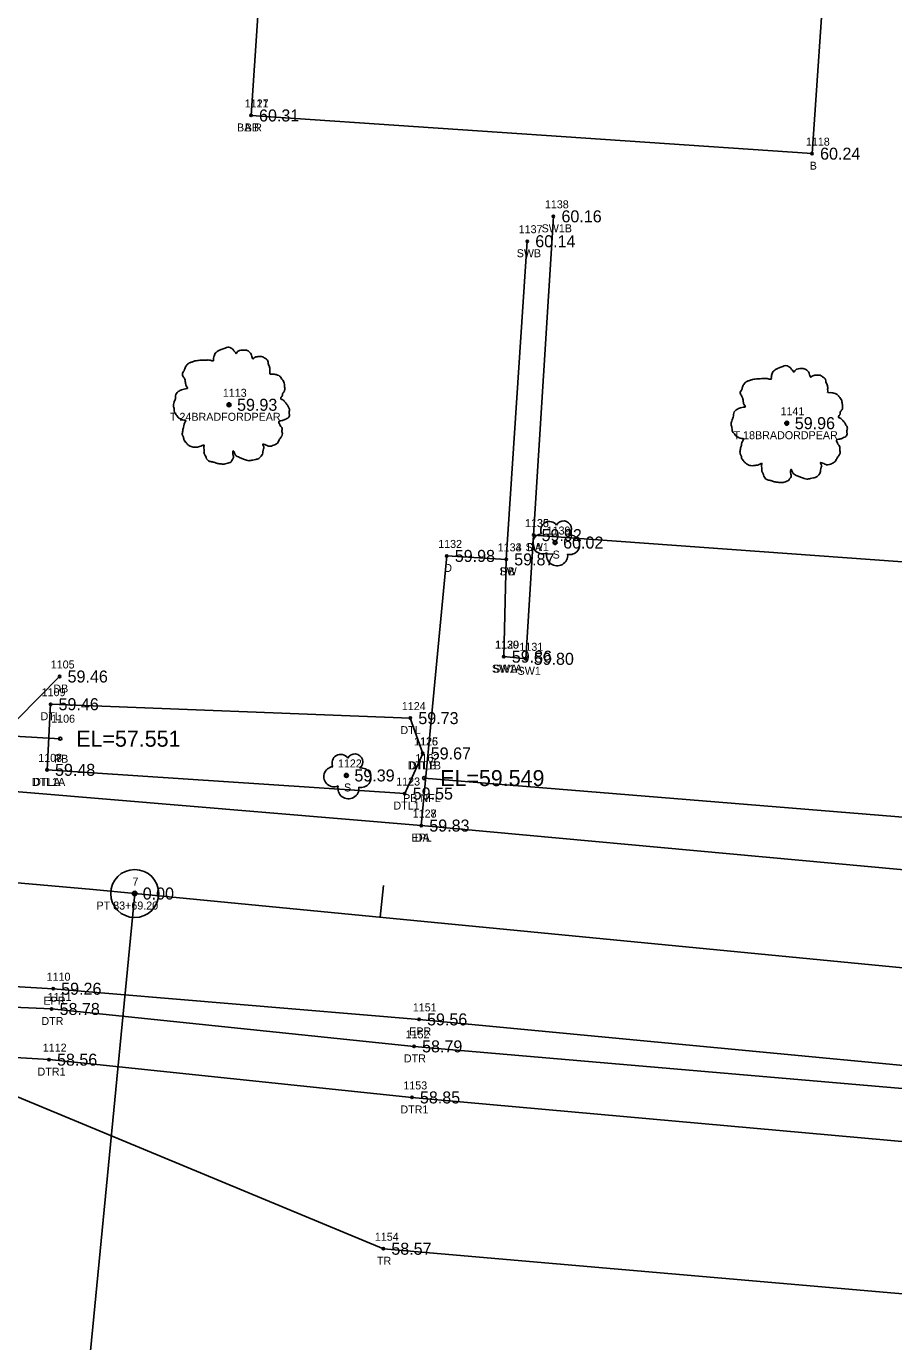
# Model space of a CAD drawing. Extents: x 2420113 to 2422887, y 845323 to 846653.
# Drawn here: x 2420746.1 to 2420854.4, y 845663.2 to 845827.5 of the extents above; entities that cross this region are included whole.
import ezdxf

# ---------------------------------------------------------------- set-up
doc = ezdxf.new("R2010")
doc.units = 0
for name, color, linetype in [('RD_EX_Bldg', 7, 'Continuous'), ('RD_EX_Bldg_txCode', 7, 'Continuous'), ('RD_EX_Conc', 7, 'Continuous'), ('RD_EX_Conc_txCode', 7, 'Continuous'), ('RD_EX_DR_Pipe', 7, 'Continuous'), ('RD_EX_DR_Pipe_txCode', 7, 'Continuous'), ('RD_EX_Driveway', 7, 'Continuous'), ('RD_EX_Driveway_txCode', 7, 'Continuous'), ('RD_EX_H2O', 7, 'Continuous'), ('RD_EX_H2O_txCode', 7, 'Continuous'), ('RD_EX_Road', 7, 'Continuous'), ('RD_EX_Road_txCode', 7, 'Continuous'), ('RD_EX_TX_Bldg_ELEV', 7, 'Continuous'), ('RD_EX_TX_Conc_ELEV', 7, 'Continuous'), ('RD_EX_TX_Driveway_ELEV', 7, 'Continuous'), ('RD_EX_TX_H2O_ELEV', 7, 'Continuous'), ('RD_EX_TX_Road_ELEV', 7, 'Continuous'), ('RD_EX_TX_VEG_ELEV', 7, 'Continuous'), ('RD_EX_VEG', 7, 'Continuous'), ('RD_EX_VEG_txCode', 7, 'Continuous'), ('RD_HC_Cl', 7, 'Continuous'), ('RD_HC_Data', 7, 'Continuous'), ('RD_HC_Data_Tic', 7, 'Continuous'), ('RD_HC_Survey_ELEV', 7, 'Continuous'), ('RD_HC_txCode', 7, 'Continuous'), ('RD_SMD_Locator', 7, 'Continuous'), ('RD_TX_Pipe_ElevEX', 7, 'Continuous')]:
    doc.layers.add(name, color=color, linetype=linetype)

msp = doc.modelspace()

# ---------------------------------------------------------------- linework, layer by layer
at = {"layer": 'RD_EX_Bldg'}
msp.add_lwpolyline([(2420774.14, 845816.35), (2420844.19, 845811.58), (2420845.89, 845836.52), (2420775.84, 845841.29), (2420774.14, 845816.35)], dxfattribs=at)
at = {"layer": 'RD_EX_Conc'}
for points in [[(2420805.7, 845748.75), (2420808.43, 845748.48), (2420809.42, 845763.93), (2420811.9, 845803.75)], [(2420805.7, 845748.75), (2420806, 845760.9), (2420808.63, 845800.64)]]:
    msp.add_lwpolyline(points, dxfattribs=at)
at = {"layer": 'RD_EX_DR_Pipe'}
for p, q in [((2420720.48, 845740.22), (2420750.32, 845738.5)), ((2420903.06, 845724.83), (2420795.76, 845733.58))]:
    msp.add_line(p, q, dxfattribs=at)
at = {"layer": 'RD_EX_Driveway'}
msp.add_line((2420736.67, 845732.56), (2420750.24, 845746.27), dxfattribs=at)
for points in [[(2420809.42, 845763.93), (2420862.38, 845760.08), (2420865.05, 845760.09), (2420893.89, 845756.85), (2420889.7, 845718.98)], [(2420795.4, 845727.65), (2420798.58, 845761.33), (2420806, 845760.9)]]:
    msp.add_lwpolyline(points, dxfattribs=at)
at = {"layer": 'RD_EX_H2O'}
for points in [[(2420748.67, 845734.61), (2420749.11, 845742.81), (2420794.03, 845741.07), (2420795.58, 845736.66)], [(2420748.67, 845734.61), (2420793.33, 845731.65), (2420795.58, 845736.66)], [(2420681.02, 845707.72), (2420749.24, 845704.74), (2420794.5, 845700.07), (2420899.98, 845690.96), (2421017.54, 845678.31), (2421112.89, 845668.07), (2421174.6, 845666.39), (2421234.64, 845664.08), (2421293.38, 845665.28), (2421351.67, 845667.88), (2421422.34, 845677.35), (2421426.88, 845673.47), (2421424.22, 845667.22)], [(2420681.1, 845702.44), (2420748.92, 845698.41), (2420794.23, 845693.69), (2420899.45, 845684.25), (2421017.43, 845671.31), (2421111.87, 845660.39), (2421174.2, 845656.63), (2421235.06, 845654.38), (2421294.9, 845653.67), (2421353.19, 845655.89), (2421424.22, 845667.22)]]:
    msp.add_lwpolyline(points, dxfattribs=at)
at = {"layer": 'RD_EX_Road'}
for points in [[(2420388.28, 845680.39), (2420441.29, 845692.04), (2420492.62, 845700.7), (2420553.92, 845707.41), (2420607.69, 845710.85), (2420682.38, 845711.26), (2420749.44, 845707.27), (2420795.12, 845703.44), (2420900.28, 845693.42), (2421017.17, 845682.19), (2421113.9, 845672.97), (2421174.87, 845668.16), (2421234.59, 845666.13), (2421293, 845667.25), (2421351.24, 845671.5), (2421419.82, 845681.17), (2421463.19, 845688.63), (2421558.82, 845713.18), (2421614.57, 845730.45), (2421670.73, 845751.42), (2421735.61, 845780.5), (2421750.75, 845787.87), (2421744.67, 845798.22), (2421739.21, 845808.11)], [(2420376.35, 845701.93), (2420403.68, 845709.11), (2420436.45, 845715.41), (2420465.85, 845720.8), (2420487.58, 845724.76), (2420551.29, 845731.53), (2420607.05, 845734.89), (2420658.72, 845735.59), (2420682.86, 845735.47), (2420736.67, 845732.56), (2420795.4, 845727.65), (2420889.7, 845718.98), (2420911.08, 845716.87), (2420953.91, 845713.71), (2420998.34, 845708.25), (2421018.47, 845706.55), (2421116.02, 845696.98), (2421176.98, 845692), (2421235.85, 845690.14), (2421292.32, 845691.44), (2421350.22, 845695.49), (2421412.35, 845704.28)]]:
    msp.add_lwpolyline(points, dxfattribs=at)
at = {"layer": 'RD_EX_VEG'}
msp.add_lwpolyline([(2420391.44, 845659.63), (2420497.12, 845682.87), (2420554.96, 845697.51), (2420665.26, 845702.88), (2420735.64, 845697.65), (2420790.66, 845674.79), (2421018.22, 845655.05), (2421176.12, 845636.22), (2421296.76, 845636.57), (2421411.61, 845653.11), (2421415.24, 845569.55)], dxfattribs=at)
for centre, radius in [((2420771.4, 845780.21), 0.25), ((2420771.39, 845780.19), 0.0001), ((2420841.03, 845777.91), 0.25), ((2420841.02, 845777.89), 0.0001), ((2420812.11, 845763), 0.25), ((2420786.05, 845733.91), 0.25)]:
    msp.add_circle(centre, radius, dxfattribs=at)
for centre, radius, start, end in [((2420811.39, 845764.55), 1.08, 34.9763, 204.756), ((2420813.16, 845764.71), 0.995, 308.7626, 152.0467), ((2420810.55, 845762.85), 1.26, 96.4518, 294.734), ((2420813.95, 845762.72), 1.22, 256.5667, 98.1046), ((2420812.36, 845761.41), 1.32, 166.8827, 5.7589), ((2420785.33, 845735.46), 1.08, 34.9763, 204.756), ((2420787.1, 845735.61), 0.995, 308.7626, 152.0467), ((2420784.49, 845733.75), 1.26, 96.4518, 294.734), ((2420787.89, 845733.63), 1.22, 256.5667, 98.1046), ((2420786.3, 845732.31), 1.32, 166.8827, 5.7589)]:
    msp.add_arc(centre, radius, start, end, dxfattribs=at)
for points in [[(2420771.53, 845787.38), (2420771.23, 845787.4), (2420770.91, 845787.3), (2420770.66, 845787.2), (2420770.43, 845787.13), (2420770.21, 845787.03), (2420769.91, 845786.85), (2420769.68, 845786.65), (2420769.56, 845786.4), (2420769.51, 845786.18), (2420769.46, 845785.9), (2420769.46, 845785.73), (2420769.33, 845785.7), (2420769.18, 845785.73), (2420768.93, 845785.8), (2420768.68, 845785.8), (2420768.43, 845785.8), (2420768.08, 845785.78), (2420767.73, 845785.78), (2420767.46, 845785.73), (2420767.13, 845785.68), (2420766.76, 845785.55), (2420766.41, 845785.43), (2420766.11, 845785.18), (2420765.86, 845784.7), (2420765.73, 845784.35), (2420765.58, 845784.1), (2420765.73, 845783.65), (2420765.91, 845783.3), (2420765.93, 845783.1), (2420766.01, 845782.68), (2420766.11, 845782.46), (2420766.23, 845782.26), (2420766.16, 845782.23), (2420765.78, 845782.18), (2420765.48, 845782.08), (2420765.06, 845781.86), (2420764.83, 845781.63), (2420764.73, 845781.31), (2420764.71, 845780.96), (2420764.61, 845780.76), (2420764.53, 845780.48), (2420764.51, 845780.41), (2420764.46, 845780.08), (2420764.56, 845779.63), (2420764.58, 845779.28), (2420764.71, 845779.06), (2420764.86, 845778.88), (2420765.03, 845778.63), (2420765.43, 845778.41), (2420765.76, 845778.31), (2420765.96, 845778.28), (2420765.78, 845777.78), (2420765.73, 845777.43), (2420765.61, 845777.03), (2420765.61, 845776.96), (2420765.56, 845776.48), (2420765.71, 845776.16), (2420765.78, 845775.78), (2420765.96, 845775.56), (2420766.23, 845775.26), (2420766.56, 845775.03), (2420767.06, 845774.91), (2420767.46, 845774.93), (2420768.03, 845775.11), (2420768.28, 845775.18), (2420768.26, 845775.01), (2420768.28, 845774.63), (2420768.28, 845774.21), (2420768.43, 845773.88), (2420768.53, 845773.61), (2420768.68, 845773.36), (2420769.01, 845773.13), (2420769.41, 845773.06), (2420769.83, 845772.91), (2420770.28, 845772.83), (2420770.78, 845772.81), (2420771.38, 845772.96), (2420771.66, 845773.08), (2420771.76, 845773.26), (2420771.95, 845773.63), (2420771.9, 845773.86), (2420771.93, 845774.46), (2420772.03, 845774.28), (2420772.2, 845773.93), (2420772.7, 845773.63), (2420773.1, 845773.46), (2420773.58, 845773.31), (2420773.88, 845773.23), (2420774.35, 845773.31), (2420774.73, 845773.38), (2420775.1, 845773.51), (2420775.4, 845773.78), (2420775.58, 845774.06), (2420775.63, 845774.33), (2420775.7, 845774.71), (2420775.75, 845774.88)], [(2420775.75, 845774.88), (2420775.68, 845775.06), (2420775.63, 845775.31), (2420775.7, 845775.28), (2420775.88, 845775.23), (2420776.15, 845775.11), (2420776.38, 845775.03), (2420776.7, 845775.06), (2420776.98, 845775.16), (2420777.43, 845775.43), (2420777.7, 845775.91), (2420777.98, 845776.31), (2420778.05, 845776.63), (2420778, 845776.86), (2420777.98, 845777.36), (2420777.78, 845777.61), (2420777.73, 845777.73), (2420777.63, 845778.13), (2420777.7, 845778.18), (2420777.98, 845778.23), (2420778.35, 845778.36), (2420778.63, 845778.48), (2420778.85, 845778.66), (2420778.93, 845778.88), (2420778.9, 845779.28), (2420778.95, 845779.68), (2420778.88, 845779.83), (2420778.78, 845779.98), (2420778.7, 845780.18), (2420778.55, 845780.33), (2420778.45, 845780.48), (2420778.35, 845780.58), (2420778.23, 845780.73), (2420778.05, 845780.86), (2420777.9, 845780.91), (2420777.85, 845781.06), (2420778, 845781.26), (2420778.05, 845781.36), (2420778.08, 845781.58), (2420778.3, 845781.93), (2420778.35, 845782.33), (2420778.3, 845782.76), (2420778.25, 845783.03), (2420778.1, 845783.3), (2420777.9, 845783.55), (2420777.78, 845783.73), (2420777.6, 845783.85), (2420777.28, 845783.98), (2420777.03, 845784.03), (2420776.68, 845784.03), (2420776.48, 845784.08), (2420776.5, 845784.13), (2420776.5, 845784.28), (2420776.5, 845784.55), (2420776.43, 845785), (2420776.28, 845785.5), (2420776.28, 845785.53), (2420776.18, 845785.78), (2420775.95, 845785.98), (2420775.78, 845786.08), (2420775.58, 845786.2), (2420775.33, 845786.23), (2420775.03, 845786.23), (2420774.75, 845786.18), (2420774.55, 845786.08), (2420774.38, 845785.95), (2420774.3, 845786.1), (2420774.2, 845786.4), (2420774.15, 845786.55), (2420774, 845786.73), (2420773.78, 845786.93), (2420773.33, 845787.05), (2420772.7, 845786.98), (2420772.4, 845786.78), (2420772.25, 845786.6), (2420772.2, 845786.73), (2420772, 845786.93), (2420771.9, 845787.1), (2420771.73, 845787.23), (2420771.58, 845787.33), (2420771.48, 845787.38)], [(2420841.17, 845785.07), (2420840.87, 845785.1), (2420840.54, 845785), (2420840.29, 845784.9), (2420840.07, 845784.82), (2420839.84, 845784.72), (2420839.54, 845784.55), (2420839.32, 845784.35), (2420839.19, 845784.1), (2420839.14, 845783.87), (2420839.09, 845783.6), (2420839.09, 845783.42), (2420838.97, 845783.4), (2420838.82, 845783.42), (2420838.57, 845783.5), (2420838.32, 845783.5), (2420838.07, 845783.5), (2420837.72, 845783.47), (2420837.37, 845783.47), (2420837.09, 845783.42), (2420836.77, 845783.37), (2420836.39, 845783.25), (2420836.04, 845783.12), (2420835.74, 845782.87), (2420835.49, 845782.4), (2420835.37, 845782.05), (2420835.22, 845781.8), (2420835.37, 845781.35), (2420835.54, 845781), (2420835.57, 845780.8), (2420835.64, 845780.38), (2420835.74, 845780.15), (2420835.87, 845779.95), (2420835.79, 845779.93), (2420835.42, 845779.88), (2420835.12, 845779.78), (2420834.69, 845779.55), (2420834.47, 845779.33), (2420834.37, 845779), (2420834.34, 845778.65), (2420834.24, 845778.45), (2420834.17, 845778.18), (2420834.14, 845778.1), (2420834.09, 845777.78), (2420834.19, 845777.33), (2420834.22, 845776.98), (2420834.34, 845776.75), (2420834.49, 845776.58), (2420834.67, 845776.33), (2420835.07, 845776.1), (2420835.39, 845776), (2420835.59, 845775.98), (2420835.42, 845775.48), (2420835.37, 845775.13), (2420835.24, 845774.73), (2420835.24, 845774.65), (2420835.19, 845774.18), (2420835.34, 845773.85), (2420835.42, 845773.48), (2420835.59, 845773.25), (2420835.87, 845772.95), (2420836.19, 845772.73), (2420836.69, 845772.6), (2420837.09, 845772.63), (2420837.67, 845772.8), (2420837.92, 845772.88), (2420837.89, 845772.7), (2420837.92, 845772.33), (2420837.92, 845771.9), (2420838.07, 845771.58), (2420838.17, 845771.3), (2420838.32, 845771.05), (2420838.64, 845770.83), (2420839.04, 845770.75), (2420839.47, 845770.6), (2420839.92, 845770.53), (2420840.42, 845770.5), (2420841.02, 845770.65), (2420841.29, 845770.78), (2420841.39, 845770.95), (2420841.59, 845771.33), (2420841.54, 845771.55), (2420841.57, 845772.15), (2420841.67, 845771.98), (2420841.84, 845771.63), (2420842.34, 845771.33), (2420842.74, 845771.15), (2420843.22, 845771), (2420843.52, 845770.93), (2420843.99, 845771), (2420844.36, 845771.08), (2420844.74, 845771.2), (2420845.04, 845771.48), (2420845.21, 845771.75), (2420845.26, 845772.03), (2420845.34, 845772.4), (2420845.39, 845772.58)], [(2420845.39, 845772.58), (2420845.31, 845772.75), (2420845.26, 845773), (2420845.34, 845772.98), (2420845.51, 845772.93), (2420845.79, 845772.8), (2420846.01, 845772.73), (2420846.34, 845772.75), (2420846.61, 845772.85), (2420847.06, 845773.13), (2420847.34, 845773.6), (2420847.61, 845774), (2420847.69, 845774.33), (2420847.64, 845774.55), (2420847.61, 845775.05), (2420847.41, 845775.3), (2420847.36, 845775.43), (2420847.26, 845775.83), (2420847.34, 845775.88), (2420847.61, 845775.93), (2420847.99, 845776.05), (2420848.26, 845776.18), (2420848.49, 845776.35), (2420848.56, 845776.58), (2420848.54, 845776.98), (2420848.59, 845777.38), (2420848.51, 845777.53), (2420848.41, 845777.68), (2420848.34, 845777.88), (2420848.19, 845778.03), (2420848.09, 845778.18), (2420847.99, 845778.28), (2420847.86, 845778.43), (2420847.69, 845778.55), (2420847.54, 845778.6), (2420847.49, 845778.75), (2420847.64, 845778.95), (2420847.69, 845779.05), (2420847.71, 845779.28), (2420847.94, 845779.63), (2420847.99, 845780.03), (2420847.94, 845780.45), (2420847.89, 845780.73), (2420847.74, 845781), (2420847.54, 845781.25), (2420847.41, 845781.42), (2420847.24, 845781.55), (2420846.91, 845781.67), (2420846.66, 845781.72), (2420846.31, 845781.72), (2420846.11, 845781.77), (2420846.14, 845781.82), (2420846.14, 845781.97), (2420846.14, 845782.25), (2420846.06, 845782.7), (2420845.91, 845783.2), (2420845.91, 845783.22), (2420845.81, 845783.47), (2420845.59, 845783.67), (2420845.41, 845783.77), (2420845.21, 845783.9), (2420844.96, 845783.92), (2420844.66, 845783.92), (2420844.39, 845783.87), (2420844.19, 845783.77), (2420844.01, 845783.65), (2420843.94, 845783.8), (2420843.84, 845784.1), (2420843.79, 845784.25), (2420843.64, 845784.42), (2420843.42, 845784.62), (2420842.97, 845784.75), (2420842.34, 845784.67), (2420842.04, 845784.47), (2420841.89, 845784.3), (2420841.84, 845784.42), (2420841.64, 845784.62), (2420841.54, 845784.8), (2420841.37, 845784.92), (2420841.22, 845785.02), (2420841.12, 845785.07)]]:
    msp.add_spline(points, degree=3, dxfattribs=at)
at = {"layer": 'RD_HC_Cl'}
msp.add_line((2420759.62, 845719.16), (2421125.21, 845683.73), dxfattribs=at)
msp.add_arc((2420649.07, 844578.36), 1146.15, 84.46476, 117.6481, dxfattribs=at)
at = {"layer": 'RD_HC_Data'}
msp.add_line((2420759.62, 845719.16), (2420748.46, 845603.99), dxfattribs=at)
for radius in [3, 0.282]:
    msp.add_circle((2420759.62, 845719.16), radius, dxfattribs=at)
at = {"layer": 'RD_HC_Data_Tic'}
msp.add_line((2420790.28, 845716.19), (2420790.66, 845720.17), dxfattribs=at)
at = {"layer": 'RD_SMD_Locator'}
for centre, radius in [((2420774.14, 845816.35), 0.15), ((2420774.14, 845816.35), 0.15), ((2420844.19, 845811.58), 0.15), ((2420811.9, 845803.75), 0.15), ((2420808.63, 845800.64), 0.15), ((2420771.4, 845780.21), 0.15), ((2420841.03, 845777.91), 0.15), ((2420809.42, 845763.93), 0.15), ((2420809.42, 845763.93), 0.15), ((2420812.11, 845763), 0.15), ((2420798.58, 845761.33), 0.15), ((2420806, 845760.9), 0.15), ((2420806, 845760.9), 0.15), ((2420805.7, 845748.75), 0.15), ((2420805.7, 845748.75), 0.15), ((2420808.43, 845748.48), 0.15), ((2420750.24, 845746.27), 0.15), ((2420749.11, 845742.81), 0.15), ((2420794.03, 845741.07), 0.15), ((2420750.32, 845738.5), 0.2), ((2420795.58, 845736.66), 0.15), ((2420795.58, 845736.66), 0.15), ((2420748.67, 845734.61), 0.15), ((2420748.67, 845734.61), 0.15), ((2420786.05, 845733.91), 0.15), ((2420795.76, 845733.58), 0.2), ((2420793.33, 845731.65), 0.15), ((2420795.4, 845727.65), 0.15), ((2420795.4, 845727.65), 0.15), ((2420759.62, 845719.16), 0.15), ((2420749.44, 845707.27), 0.15), ((2420749.24, 845704.74), 0.15), ((2420795.12, 845703.44), 0.15), ((2420794.5, 845700.07), 0.15), ((2420748.92, 845698.41), 0.15), ((2420794.23, 845693.69), 0.15), ((2420790.66, 845674.79), 0.15)]:
    msp.add_circle(centre, radius, dxfattribs=at)

# ---------------------------------------------------------------- texts
at = {"layer": 'RD_EX_Bldg_txCode'}
for s, p in [('1121', (2420773.36, 845817.35)), ('1117', (2420773.36, 845817.35)), ('BA R', (2420772.39, 845814.35)), ('BB', (2420773.36, 845814.35)), ('1118', (2420843.42, 845812.58)), ('B', (2420843.89, 845809.58))]:
    msp.add_text(s, height=1, dxfattribs=at).set_placement(p)
at = {"layer": 'RD_EX_Conc_txCode'}
for s, p in [('1138', (2420810.83, 845804.75)), ('1137', (2420807.56, 845801.64)), ('SW1B', (2420810.42, 845801.75)), ('SWB', (2420807.31, 845798.64)), ('1135', (2420808.36, 845764.93)), ('1134', (2420804.94, 845761.9)), ('SW1', (2420808.42, 845761.93)), ('SW', (2420805.16, 845758.9)), ('1130', (2420804.6, 845749.75)), ('1129', (2420804.64, 845749.75)), ('1131', (2420807.65, 845749.48)), ('SW1A', (2420804.21, 845746.75)), ('SWA', (2420804.37, 845746.75)), ('SW1', (2420807.42, 845746.48))]:
    msp.add_text(s, height=1, dxfattribs=at).set_placement(p)
at = {"layer": 'RD_EX_DR_Pipe_txCode'}
for s, p in [('1106', (2420749.19, 845740.5)), ('PB', (2420749.54, 845735.5)), ('1162', (2420794.67, 845735.58)), ('PB NFL', (2420793.13, 845730.58))]:
    msp.add_text(s, height=1, dxfattribs=at).set_placement(p)
at = {"layer": 'RD_EX_Driveway_txCode'}
for s, p in [('1136', (2420808.34, 845764.93)), ('1132', (2420797.51, 845762.33)), ('1133', (2420804.94, 845761.9)), ('DA', (2420808.63, 845761.93)), ('D', (2420798.27, 845759.33)), ('DB', (2420805.22, 845758.9)), ('1105', (2420749.14, 845747.27)), ('DB', (2420749.46, 845744.27)), ('1128', (2420794.33, 845728.65)), ('DA', (2420794.6, 845725.65))]:
    msp.add_text(s, height=1, dxfattribs=at).set_placement(p)
at = {"layer": 'RD_EX_H2O_txCode'}
for s, p in [('1109', (2420748, 845743.81)), ('1124', (2420792.97, 845742.07)), ('DTL', (2420747.86, 845740.81)), ('DTL', (2420792.79, 845739.07)), ('1126', (2420794.49, 845737.66)), ('1125', (2420794.52, 845737.66)), ('1107', (2420747.57, 845735.61)), ('1108', (2420747.57, 845735.61)), ('DTL1B', (2420793.7, 845734.66)), ('DTLB', (2420793.86, 845734.66)), ('DTL1A', (2420746.78, 845732.61)), ('DTLA', (2420746.94, 845732.61)), ('1123', (2420792.27, 845732.65)), ('DTL1', (2420791.92, 845729.65)), ('1111', (2420748.75, 845705.74)), ('DTR', (2420747.97, 845702.74)), ('1152', (2420793.44, 845701.07)), ('1112', (2420748.14, 845699.41)), ('DTR', (2420793.23, 845698.07)), ('DTR1', (2420747.49, 845696.41)), ('1153', (2420793.16, 845694.69)), ('DTR1', (2420792.79, 845691.69))]:
    msp.add_text(s, height=1, dxfattribs=at).set_placement(p)
at = {"layer": 'RD_EX_Road_txCode'}
for s, p in [('1127', (2420794.33, 845728.65)), ('EPL', (2420794.19, 845725.65)), ('1110', (2420748.62, 845708.27)), ('EPR', (2420748.22, 845705.27)), ('1151', (2420794.34, 845704.44)), ('EPR', (2420793.89, 845701.44))]:
    msp.add_text(s, height=1, dxfattribs=at).set_placement(p)
at = {"layer": 'RD_EX_TX_Bldg_ELEV'}
for s, p in [('60.31', (2420775.14, 845815.6)), ('60.31', (2420775.14, 845815.6)), ('60.24', (2420845.19, 845810.83))]:
    msp.add_text(s, height=1.5, dxfattribs=at).set_placement(p)
at = {"layer": 'RD_EX_TX_Conc_ELEV'}
for s, p in [('60.16', (2420812.9, 845803)), ('60.14', (2420809.63, 845799.89)), ('59.92', (2420810.42, 845763.18)), ('59.87', (2420807, 845760.15)), ('59.86', (2420806.7, 845748)), ('59.86', (2420806.7, 845748)), ('59.80', (2420809.43, 845747.73))]:
    msp.add_text(s, height=1.5, dxfattribs=at).set_placement(p)
at = {"layer": 'RD_EX_TX_Driveway_ELEV'}
for s, p in [('59.92', (2420810.42, 845763.18)), ('59.98', (2420799.58, 845760.58)), ('59.87', (2420807, 845760.15)), ('59.46', (2420751.24, 845745.52)), ('59.83', (2420796.4, 845726.9))]:
    msp.add_text(s, height=1.5, dxfattribs=at).set_placement(p)
at = {"layer": 'RD_EX_TX_H2O_ELEV'}
for s, p in [('59.46', (2420750.11, 845742.06)), ('59.73', (2420795.03, 845740.32)), ('59.67', (2420796.58, 845735.91)), ('59.67', (2420796.58, 845735.91)), ('59.48', (2420749.67, 845733.86)), ('59.48', (2420749.67, 845733.86)), ('59.55', (2420794.33, 845730.9)), ('58.78', (2420750.24, 845703.99)), ('58.79', (2420795.5, 845699.32)), ('58.56', (2420749.92, 845697.66)), ('58.85', (2420795.23, 845692.94))]:
    msp.add_text(s, height=1.5, dxfattribs=at).set_placement(p)
at = {"layer": 'RD_EX_TX_Road_ELEV'}
for s, p in [('59.83', (2420796.4, 845726.9)), ('59.26', (2420750.44, 845706.52)), ('59.56', (2420796.12, 845702.69))]:
    msp.add_text(s, height=1.5, dxfattribs=at).set_placement(p)
at = {"layer": 'RD_EX_TX_VEG_ELEV'}
for s, p in [('59.93', (2420772.4, 845779.46)), ('59.96', (2420842.03, 845777.16)), ('60.02', (2420813.11, 845762.25)), ('59.39', (2420787.05, 845733.16)), ('58.57', (2420791.66, 845674.04))]:
    msp.add_text(s, height=1.5, dxfattribs=at).set_placement(p)
at = {"layer": 'RD_EX_VEG_txCode'}
for s, p in [('1113', (2420770.62, 845781.21)), ('T 24BRADFORDPEAR', (2420764.02, 845778.21)), ('1141', (2420840.25, 845778.91)), ('T 18BRADORDPEAR', (2420834.39, 845775.91)), ('1139', (2420811.05, 845764)), ('S', (2420811.8, 845761)), ('1122', (2420784.99, 845734.91)), ('S', (2420785.75, 845731.91)), ('1154', (2420789.6, 845675.79)), ('TR', (2420789.87, 845672.79))]:
    msp.add_text(s, height=1, dxfattribs=at).set_placement(p)
at = {"layer": 'RD_HC_Survey_ELEV'}
msp.add_text('0.00', height=1.5, dxfattribs=at).set_placement((2420760.62, 845718.41))
at = {"layer": 'RD_HC_txCode'}
for s, p in [('7', (2420759.34, 845720.16)), ('PT 83+69.20', (2420754.85, 845717.16))]:
    msp.add_text(s, height=1, dxfattribs=at).set_placement(p)
at = {"layer": 'RD_TX_Pipe_ElevEX'}
for s, p in [('EL=57.551', (2420752.32, 845737.5)), ('EL=59.549', (2420797.76, 845732.58))]:
    msp.add_text(s, height=2, dxfattribs=at).set_placement(p)

doc.saveas('drawing.dxf')
